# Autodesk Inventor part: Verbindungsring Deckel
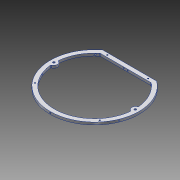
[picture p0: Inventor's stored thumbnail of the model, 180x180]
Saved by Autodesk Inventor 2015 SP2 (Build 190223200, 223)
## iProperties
Created: 2012-10
Part Number: Verbindungsring Deckel
Material: Aluminium 6061
Document SubType Name: Modeling
Designer: rYan
Density: 2.71 g/cm^3
Mass: 51.3916 g
Surface Area: 139.478 cm^2
Volume: 18.9637 cm^3
Appearance: Aluminium - flach
Author: rYan
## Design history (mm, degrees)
sketch "Skizze1"
  geometry: L1 (0, 100.2)-(0, -118.2) reference; L2 (-121.8, 0)-(121.8, 0) reference; L3 (-52.991, 69)-(-32.512, 69); L4 (32.512, 69)-(52.991, 69); L5 (-50.2, 61)-(50.2, 61); L6 (-32.512, 69)-(32.512, 69); A1 r 87 centre (0, 0) between (-52.991, 69) and (52.991, 69); A2 r 7 centre (-80, 0) between (-78.7, -6.878) and (-78.7, 6.878); A3 r 7 centre (80, 0) between (78.7, 6.878) and (78.7, -6.878); A4 r 79 centre (0, 0) between (-50.2, 61) and (-78.7, 6.878); A5 r 79 centre (0, 0) between (-78.7, -6.878) and (78.7, -6.878); A6 r 79 centre (0, 0) between (78.7, 6.878) and (50.2, 61); 1 further point
  constraints: 12 point on circle, 8 end point, 6 centre point, 4 parallel, 2 coincident, 2 point on line, 1 symmetric about line
  dimensions: "d0" = 174 diameter of A1; "d4" = 61 distance between parallel lines of L2 L5; "d5" = 8 distance between parallel lines of L6 L5; "d98" = 14 diameter of A2; "d99" = 14 diameter of A3 (= d98); "d100" = 160 distance of A3.centre A2.centre; "d120" = 79 radius of A4; "d121" = 79 radius of A6 (= d120); "d122" = 79 radius of A5 (= d120)
extrude "Extrusion1" new body sketch "Skizze1" stored distance "d6" = 5; taper "d7" = 0 deg
workplane "Arbeitsebene6"
workaxis "Arbeitsachse2"
sketch "Skizze10" dims "d77" = 166
  geometry: L1 (-50.2, 61)-(50.2, 61) reference; L2 (52.991, 69)-(-52.991, 69) reference; L3 (0, 0)-(63.582, -53.351); L4 (-121.8, 0)-(121.8, 0) reference; L5 (0, 69)-(0, 61); L6 (-40, 65)-(40, 65); A1 r 87 centre (0, 0) between (-52.991, 69) and (52.991, 69) reference; 2 further points
  constraints: 6 end point, 3 coincident, 2 midpoint, 1 perpendicular, 1 symmetric about line, 3 other
  dimensions: "d80" = 40 deg angle of L4 L3; "d82" = 80 distance of L6.start L6.end; "d125" = 65 distance between parallel lines of L4 L6
hole "Bohrung6" sketch "Skizze10" at (63.582, -53.351), (40, 65) diameter "d83" = 2.459; stored, may be unused: countersink angle "d87" = 90 deg, drill point angle "d89" = 118 deg; dims "d84" = 6, "d85" = 4, "d86" = 2, "d88" = 8.8
fillet "Rundung1" dims "d90" = 2
fillet "Rundung2" dims "d108" = 2
mirror "Spiegeln3"
workplane "Arbeitsebene8"
sketch "Skizze16"
  geometry: 2 further points
  constraints: 1 coincident
hole "Bohrung9" sketch "Skizze16" at (0, 0) diameter "d130" = 2.459; stored, may be unused: countersink angle "d134" = 90 deg, drill point angle "d136" = 118 deg; dims "d131" = 6, "d132" = 4, "d133" = 2, "d135" = 12
pattern_circular "Runde Anordnung4" dims angle "d138" = 136 deg
sketch "Skizze17"
  geometry: L1 (0, 0)-(0, 5) reference; L2 (105.981, 0)-(0, 0) reference; L3 (105.981, 5)-(105.981, 0) reference; L4 (0, 5)-(105.981, 5) reference; L5 (105.981, 5)-(105.981, 0) reference; L6 (105.981, 2.5)-(0, 2.5); L7 (-34.009, 0)-(139.991, 0) reference; L8 (52.991, 0)-(52.991, 5); L9 (0, 5)-(105.981, 5) reference; 3 further points
  constraints: 4 end point, 4 midpoint, 2 point on line, 1 symmetric about line
  dimensions: "d140" = 8 distance of point (48.991, 2.5) point (56.991, 2.5)
hole "Bohrung10" sketch "Skizze17" at (56.991, 2.5), (48.991, 2.5) diameter "d141" = 2.459; stored, may be unused: countersink angle "d145" = 90 deg, drill point angle "d147" = 118 deg; dims "d142" = 6, "d143" = 4, "d144" = 2, "d146" = 12
mirror "Spiegeln4"
sketch "Skizze18"
  geometry: A1 r 7 centre (80, 0) between (77.317, 6.465) and (77.317, -6.465) reference; A2 r 7 centre (-80, 0) between (-77.317, -6.465) and (-77.317, 6.465) reference; 3 further points
  constraints: 2 coincident
hole "Bohrung11" sketch "Skizze18" at (80, 0), (-80, 0) diameter "d148" = 4.2; stored, may be unused: countersink angle "d152" = 90 deg, drill point angle "d154" = 118 deg; dims "d149" = 6, "d150" = 10, "d151" = 3.5, "d153" = 8
node "Volumenkörper1"
node "Projizierte Kontur2"
other parameters: "d2" = 8, "d3" = 72, "d78" = 40 deg
